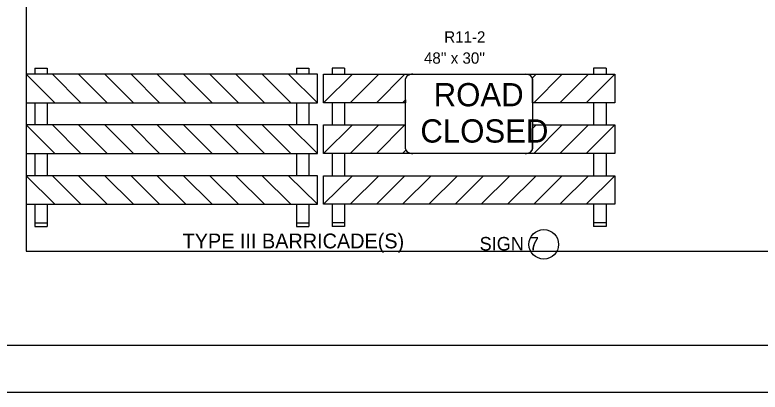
# Model space of a CAD drawing. Extents: x 1613335 to 1618399, y 897277 to 901877.
# Drawn here: x 1613956 to 1615143, y 898577 to 899179 of the extents above; entities that cross this region are included whole.
import ezdxf

# ---------------------------------------------------------------- set-up
doc = ezdxf.new("R2010")
doc.units = 0
for name, color, linetype in [('DEV BORDER CELL', 7, 'Continuous'), ('DEV TYPE 3 BARRICADE DOUBLE WITH R11-2 CELL', 7, 'Continuous'), ('Old_Level_28', 7, 'Continuous'), ('Scratch_Level_0', 7, 'Continuous'), ('Sheet Plot Border Outside CELL', 7, 'Continuous')]:
    doc.layers.add(name, color=color, linetype=linetype)

msp = doc.modelspace()

# ---------------------------------------------------------------- linework, layer by layer
at = {"layer": 'DEV BORDER CELL'}
msp.add_lwpolyline([(1618323.6, 901802.3), (1613823.6, 901802.3), (1613823.6, 898652.3), (1618323.6, 898652.3)], close=True, dxfattribs=at)
at = {"layer": 'DEV TYPE 3 BARRICADE DOUBLE WITH R11-2 CELL'}
for p, q in [((1613987.3, 899094.4), (1614007.1, 899094.4)), ((1613987.3, 899094.4), (1613987.3, 899084.6)), ((1614007.1, 899094.4), (1614007.1, 899084.6)), ((1614404.3, 899094.4), (1614424, 899094.4)), ((1614404.3, 899094.4), (1614404.3, 899084.6)), ((1614424, 899094.4), (1614424, 899084.6)), ((1614480.9, 899094.4), (1614461.2, 899094.4)), ((1614461.2, 899094.4), (1614461.2, 899084.6)), ((1614480.9, 899094.4), (1614480.9, 899084.6)), ((1614897.8, 899094.4), (1614878.1, 899094.4)), ((1614878.1, 899094.4), (1614878.1, 899084.6)), ((1614897.8, 899094.4), (1614897.8, 899084.6)), ((1614437.8, 899084.6), (1613973.6, 899084.6)), ((1613973.6, 899084.6), (1613973.6, 899039.1)), ((1614015.3, 899084.6), (1613973.6, 899084.6)), ((1613973.6, 899084.6), (1614019.1, 899039.1)), ((1614060.8, 899039.1), (1614015.3, 899084.6)), ((1614098.9, 899084.6), (1614057.1, 899084.6)), ((1614057.1, 899084.6), (1614102.6, 899039.1)), ((1614144.4, 899039.1), (1614098.9, 899084.6)), ((1614182.4, 899084.6), (1614140.6, 899084.6)), ((1614140.6, 899084.6), (1614186.2, 899039.1)), ((1614227.9, 899039.1), (1614182.4, 899084.6)), ((1614266.2, 899084.6), (1614224.4, 899084.6)), ((1614224.4, 899084.6), (1614269.9, 899039.1)), ((1614311.7, 899039.1), (1614266.2, 899084.6)), ((1614349.7, 899084.6), (1614307.9, 899084.6)), ((1614307.9, 899084.6), (1614353.4, 899039.1)), ((1614395.2, 899039.1), (1614349.7, 899084.6)), ((1614437.8, 899084.6), (1614391.5, 899084.6)), ((1614391.5, 899084.6), (1614437.8, 899039.1)), ((1614437.8, 899039.1), (1614437.8, 899084.6)), ((1614437.8, 899039.1), (1614437.8, 899084.6)), ((1614447.4, 899084.6), (1614911.6, 899084.6)), ((1614447.4, 899039.1), (1614447.4, 899084.6)), ((1614447.4, 899039.1), (1614447.4, 899084.6)), ((1614447.4, 899084.6), (1614493.7, 899084.6)), ((1614493.7, 899084.6), (1614447.4, 899039.1)), ((1614489.9, 899039.1), (1614535.5, 899084.6)), ((1614577.2, 899084.6), (1614531.7, 899039.1)), ((1614535.5, 899084.6), (1614577.2, 899084.6)), ((1614780.4, 899078.7), (1614786.3, 899084.6)), ((1614828.1, 899084.6), (1614782.5, 899039.1)), ((1614786.3, 899084.6), (1614828.1, 899084.6)), ((1614824.3, 899039.1), (1614869.8, 899084.6)), ((1614911.6, 899084.6), (1614866.1, 899039.1)), ((1614869.8, 899084.6), (1614911.6, 899084.6)), ((1614911.6, 899084.6), (1614911.6, 899039.1)), ((1614780.7, 899039.1), (1614780.7, 899077.2)), ((1613973.6, 899039.1), (1614437.8, 899039.1)), ((1613987.3, 899039.1), (1613987.3, 899003.6)), ((1614007.1, 899039.1), (1614007.1, 899003.6)), ((1614019.1, 899039.1), (1614060.8, 899039.1)), ((1614102.6, 899039.1), (1614144.4, 899039.1)), ((1614186.2, 899039.1), (1614227.9, 899039.1)), ((1614269.9, 899039.1), (1614311.7, 899039.1)), ((1614353.4, 899039.1), (1614395.2, 899039.1)), ((1614404.3, 899039.1), (1614404.3, 899003.6)), ((1614424, 899039.1), (1614424, 899003.6)), ((1614578.3, 899039.1), (1614447.4, 899039.1)), ((1614461.2, 899039.1), (1614461.2, 899003.6)), ((1614480.9, 899039.1), (1614480.9, 899003.6)), ((1614531.7, 899039.1), (1614489.9, 899039.1)), ((1614573.5, 899039.1), (1614578.3, 899043.9)), ((1614578.3, 899039.1), (1614573.5, 899039.1)), ((1614578.3, 899043.9), (1614578.3, 899039.1)), ((1614782.5, 899039.1), (1614780.7, 899039.1)), ((1614911.6, 899039.1), (1614780.7, 899039.1)), ((1614866.1, 899039.1), (1614824.3, 899039.1)), ((1614878.1, 899039.1), (1614878.1, 899003.6)), ((1614897.8, 899039.1), (1614897.8, 899003.6)), ((1614437.8, 899003.6), (1613973.6, 899003.6)), ((1613973.6, 899003.6), (1613973.6, 898958.1)), ((1614015.3, 899003.6), (1613973.6, 899003.6)), ((1613973.6, 899003.6), (1614019.1, 898958.1)), ((1614060.8, 898958.1), (1614015.3, 899003.6)), ((1614098.9, 899003.6), (1614057.1, 899003.6)), ((1614057.1, 899003.6), (1614102.6, 898958.1)), ((1614144.4, 898958.1), (1614098.9, 899003.6)), ((1614182.4, 899003.6), (1614140.6, 899003.6)), ((1614140.6, 899003.6), (1614186.2, 898958.1)), ((1614227.9, 898958.1), (1614182.4, 899003.6)), ((1614266.2, 899003.6), (1614224.4, 899003.6)), ((1614224.4, 899003.6), (1614269.9, 898958.1)), ((1614311.7, 898958.1), (1614266.2, 899003.6)), ((1614349.7, 899003.6), (1614307.9, 899003.6)), ((1614307.9, 899003.6), (1614353.4, 898958.1)), ((1614395.2, 898958.1), (1614349.7, 899003.6)), ((1614437.8, 899003.6), (1614391.5, 899003.6)), ((1614391.5, 899003.6), (1614437.8, 898958.1)), ((1614437.8, 898958.1), (1614437.8, 899003.6)), ((1614437.8, 898958.1), (1614437.8, 899003.6)), ((1614447.4, 898958.1), (1614447.4, 899003.6)), ((1614447.4, 898958.1), (1614447.4, 899003.6)), ((1614447.4, 899003.6), (1614493.7, 899003.6)), ((1614493.7, 899003.6), (1614447.4, 898958.1)), ((1614447.4, 899003.6), (1614578.3, 899003.6)), ((1614489.9, 898958.1), (1614535.5, 899003.6)), ((1614577.2, 899003.6), (1614531.7, 898958.1)), ((1614535.5, 899003.6), (1614577.2, 899003.6)), ((1614780.7, 898998), (1614786.3, 899003.6)), ((1614780.7, 899003.6), (1614911.6, 899003.6)), ((1614828.1, 899003.6), (1614782.5, 898958.1)), ((1614786.3, 899003.6), (1614828.1, 899003.6)), ((1614824.3, 898958.1), (1614869.8, 899003.6)), ((1614911.6, 899003.6), (1614866.1, 898958.1)), ((1614869.8, 899003.6), (1614911.6, 899003.6)), ((1614911.6, 899003.6), (1614911.6, 898958.1)), ((1614780.7, 898965.5), (1614780.7, 898998)), ((1614573.5, 898958.1), (1614578.8, 898963.4)), ((1613973.6, 898958.1), (1614437.8, 898958.1)), ((1613987.3, 898958.1), (1613987.3, 898922.6)), ((1614007.1, 898958.1), (1614007.1, 898922.6)), ((1614019.1, 898958.1), (1614060.8, 898958.1)), ((1614102.6, 898958.1), (1614144.4, 898958.1)), ((1614186.2, 898958.1), (1614227.9, 898958.1)), ((1614269.9, 898958.1), (1614311.7, 898958.1)), ((1614353.4, 898958.1), (1614395.2, 898958.1)), ((1614404.3, 898958.1), (1614404.3, 898922.6)), ((1614424, 898958.1), (1614424, 898922.6)), ((1614911.6, 898958.1), (1614447.4, 898958.1)), ((1614461.2, 898958.1), (1614461.2, 898922.6)), ((1614480.9, 898958.1), (1614480.9, 898922.6)), ((1614531.7, 898958.1), (1614489.9, 898958.1)), ((1614590.1, 898958.1), (1614573.5, 898958.1)), ((1614768.9, 898958.1), (1614590.1, 898958.1)), ((1614782.5, 898958.1), (1614769, 898958.1)), ((1614866.1, 898958.1), (1614824.3, 898958.1)), ((1614878.1, 898958.1), (1614878.1, 898922.6)), ((1614897.8, 898958.1), (1614897.8, 898922.6)), ((1614015.3, 898922.6), (1613973.6, 898922.6)), ((1613973.6, 898922.6), (1614019.1, 898877.1)), ((1614437.8, 898922.6), (1613973.6, 898922.6)), ((1613973.6, 898922.6), (1613973.6, 898877.1)), ((1614060.8, 898877.1), (1614015.3, 898922.6)), ((1614098.9, 898922.6), (1614057.1, 898922.6)), ((1614057.1, 898922.6), (1614102.6, 898877.1)), ((1614144.4, 898877.1), (1614098.9, 898922.6)), ((1614182.4, 898922.6), (1614140.6, 898922.6)), ((1614140.6, 898922.6), (1614186.2, 898877.1)), ((1614227.9, 898877.1), (1614182.4, 898922.6)), ((1614266.2, 898922.6), (1614224.4, 898922.6)), ((1614224.4, 898922.6), (1614269.9, 898877.1)), ((1614311.7, 898877.1), (1614266.2, 898922.6)), ((1614349.7, 898922.6), (1614307.9, 898922.6)), ((1614307.9, 898922.6), (1614353.4, 898877.1)), ((1614395.2, 898877.1), (1614349.7, 898922.6)), ((1614437.8, 898922.6), (1614391.5, 898922.6)), ((1614391.5, 898922.6), (1614437.8, 898877.1)), ((1614437.8, 898877.1), (1614437.8, 898922.6)), ((1614437.8, 898877.1), (1614437.8, 898922.6)), ((1614447.4, 898877.1), (1614447.4, 898922.6)), ((1614447.4, 898922.6), (1614493.7, 898922.6)), ((1614493.7, 898922.6), (1614447.4, 898877.1)), ((1614447.4, 898922.6), (1614911.6, 898922.6)), ((1614447.4, 898877.1), (1614447.4, 898922.6)), ((1614489.9, 898877.1), (1614535.5, 898922.6)), ((1614577.2, 898922.6), (1614531.7, 898877.1)), ((1614535.5, 898922.6), (1614577.2, 898922.6)), ((1614573.5, 898877.1), (1614619, 898922.6)), ((1614660.8, 898922.6), (1614615.3, 898877.1)), ((1614619, 898922.6), (1614660.8, 898922.6)), ((1614657.2, 898877.1), (1614702.7, 898922.6)), ((1614744.5, 898922.6), (1614699, 898877.1)), ((1614702.7, 898922.6), (1614744.5, 898922.6)), ((1614740.8, 898877.1), (1614786.3, 898922.6)), ((1614828.1, 898922.6), (1614782.5, 898877.1)), ((1614786.3, 898922.6), (1614828.1, 898922.6)), ((1614824.3, 898877.1), (1614869.8, 898922.6)), ((1614911.6, 898922.6), (1614866.1, 898877.1)), ((1614869.8, 898922.6), (1614911.6, 898922.6)), ((1614911.6, 898922.6), (1614911.6, 898877.1)), ((1613973.6, 898877.1), (1614437.8, 898877.1)), ((1613987.3, 898877.1), (1613987.3, 898841.6)), ((1614007.1, 898877.1), (1614007.1, 898841.6)), ((1614019.1, 898877.1), (1614060.8, 898877.1)), ((1614102.6, 898877.1), (1614144.4, 898877.1)), ((1614186.2, 898877.1), (1614227.9, 898877.1)), ((1614269.9, 898877.1), (1614311.7, 898877.1)), ((1614353.4, 898877.1), (1614395.2, 898877.1)), ((1614404.3, 898877.1), (1614404.3, 898841.6)), ((1614424, 898877.1), (1614424, 898841.6)), ((1614911.6, 898877.1), (1614447.4, 898877.1)), ((1614461.2, 898877.1), (1614461.2, 898841.6)), ((1614480.9, 898877.1), (1614480.9, 898841.6)), ((1614531.7, 898877.1), (1614489.9, 898877.1)), ((1614615.3, 898877.1), (1614573.5, 898877.1)), ((1614699, 898877.1), (1614657.2, 898877.1)), ((1614782.5, 898877.1), (1614740.8, 898877.1)), ((1614866.1, 898877.1), (1614824.3, 898877.1)), ((1614878.1, 898877.1), (1614878.1, 898841.6)), ((1614897.8, 898877.1), (1614897.8, 898841.6)), ((1613987.3, 898847.5), (1614007.1, 898847.5)), ((1614404.3, 898847.5), (1614424, 898847.5)), ((1614480.9, 898847.5), (1614461.2, 898847.5)), ((1614897.8, 898847.5), (1614878.1, 898847.5)), ((1613987.3, 898841.6), (1614007.1, 898841.6)), ((1614404.3, 898841.6), (1614424, 898841.6)), ((1614480.9, 898841.6), (1614461.2, 898841.6)), ((1614897.8, 898841.6), (1614878.1, 898841.6))]:
    msp.add_line(p, q, dxfattribs=at)
for points in [[(1614590.1, 899084.6), (1614768.9, 899084.6)], [(1614578.3, 898965.5), (1614578.3, 899077.2)], [(1614780.7, 899077.2), (1614780.7, 898965.5)]]:
    msp.add_lwpolyline(points, dxfattribs=at)
for centre, major_axis, start_param, end_param in [((1614590.1, 899077.2), (-11.8, 0), 4.712162, 6.283185), ((1614768.9, 899077.2), (11.8, 0), 0, 1.570796), ((1614768.9, 899077.2), (11.8, 0), 6.283185, 6.491582), ((1614590.1, 898965.5), (-11.8, 0), 0, 1.571024), ((1614590.1, 898965.5), (-11.8, 0), 0.287132, 1.570688), ((1614768.9, 898965.5), (-11.8, 0), 1.570796, 3.141593), ((1614768.9, 898965.5), (11.8, 0), 4.712389, 6.283185)]:
    msp.add_ellipse(centre, major_axis=major_axis, ratio=0.625, start_param=start_param, end_param=end_param, dxfattribs=at)
at = {"layer": 'Old_Level_28'}
msp.add_circle((1614798.6, 898813.1), 23.6, dxfattribs=at)
at = {"layer": 'Scratch_Level_0'}
msp.add_lwpolyline([(1618173.6, 901652.3), (1613973.6, 901652.3), (1613973.6, 898802.3), (1616610.1, 898802.3), (1616610.1, 899157.1), (1618173.6, 899157.1)], close=True, dxfattribs=at)
at = {"layer": 'Sheet Plot Border Outside CELL'}
msp.add_lwpolyline([(1613334.6, 898577.3), (1618398.6, 898577.3), (1618398.6, 901877.3), (1613334.6, 901877.3)], close=True, dxfattribs=at)

# ---------------------------------------------------------------- texts
at = {"layer": 'DEV TYPE 3 BARRICADE DOUBLE WITH R11-2 CELL'}
for s, height, p in [('R11-2', 18, (1614639.9, 899135.1)), ("48'' x 30''", 18, (1614607.6, 899101.4)), ('ROAD', 37.11, (1614623.1, 899033.4)), ('CLOSED', 37.11, (1614601.9, 898975.5)), ('TYPE III BARRICADE(S)', 23.645, (1614222.9, 898806.7))]:
    msp.add_text(s, height=height, dxfattribs=at).set_placement(p)
at = {"layer": 'Old_Level_28'}
msp.add_text('SIGN 7', height=21.6, dxfattribs=at).set_placement((1614696.3, 898803.3))

doc.saveas('drawing.dxf')
